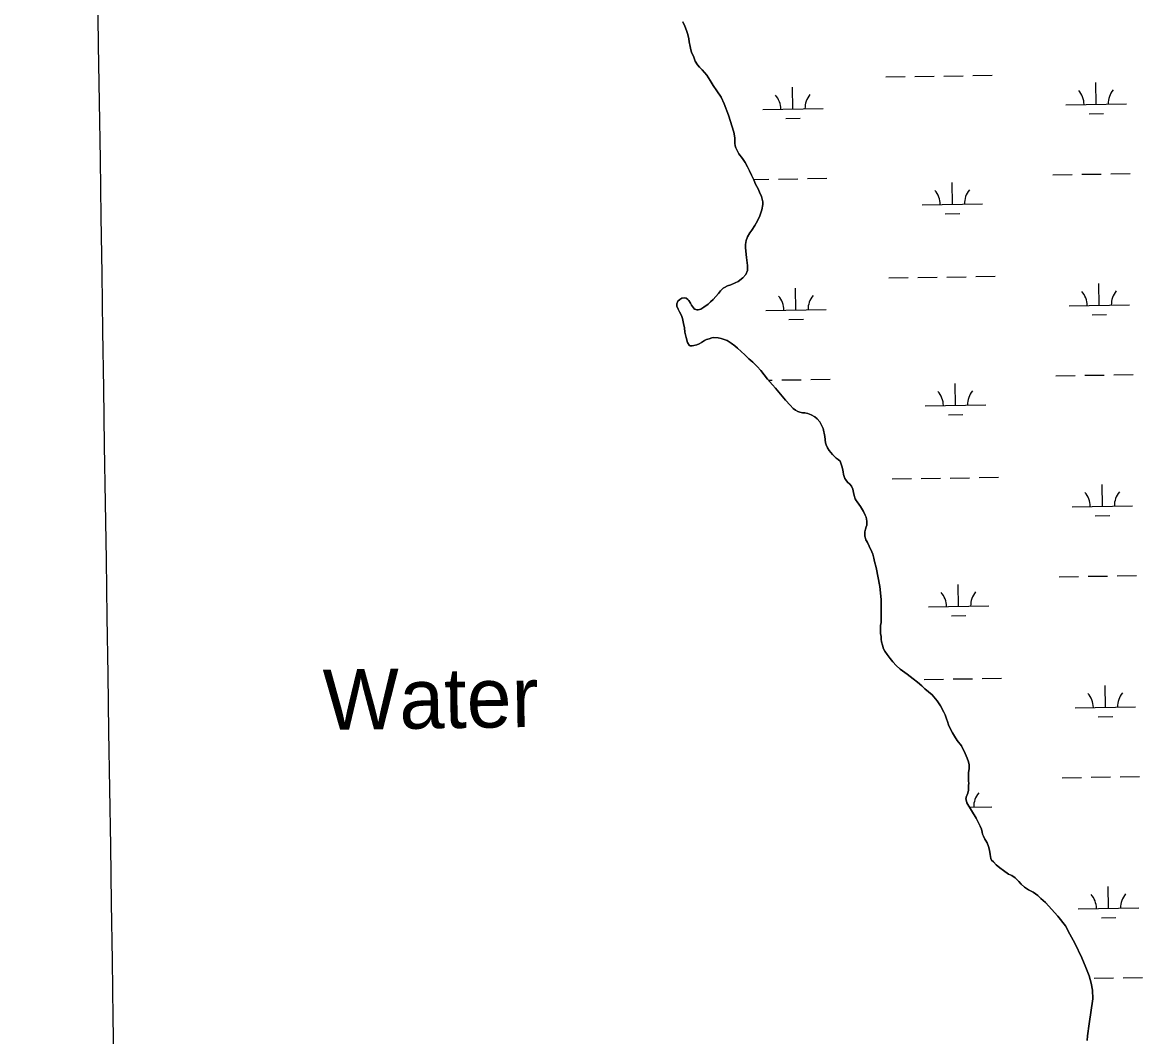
# Model space of a CAD drawing. Extents: x 3823584 to 3861785, y 301729 to 327625.
# Drawn here: x 3832860 to 3834714, y 315442 to 317121 of the extents above; entities that cross this region are included whole.
import ezdxf

# ---------------------------------------------------------------- set-up
doc = ezdxf.new("R2010")
doc.units = 0
for name, color, linetype in [('V-GRID-MAJR', 7, 'Continuous'), ('V-RIVR-IDEN', 7, 'Continuous'), ('V-TOPO-SHOR', 7, 'Continuous'), ('V-WETL-SWMP', 7, 'Continuous')]:
    doc.layers.add(name, color=color, linetype=linetype)

msp = doc.modelspace()

# ---------------------------------------------------------------- linework, layer by layer
at = {"layer": 'V-GRID-MAJR'}
msp.add_spline([(3833134.7290000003, 307237.467), (3833043.082, 313295.662), (3832951.406, 319355.783), (3832859.73, 325415.89900000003), (3832859.701, 325417.829)], degree=3, dxfattribs=at)
at = {"layer": 'V-TOPO-SHOR'}
for points in [[(3833952.44, 317121.92), (3833956.2, 317114.297), (3833958.897, 317107.457), (3833960.804, 317100.61), (3833962.448, 317093.498), (3833963.2800000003, 317088.754), (3833964.664, 317081.11100000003), (3833966.0300000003, 317075.58), (3833966.858, 317071.627), (3833970.626, 317062.95), (3833973.319, 317056.63800000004), (3833977.065, 317050.598), (3833980.2660000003, 317046.666), (3833984.528, 317042.216), (3833992.521, 317033.309), (3833998.139, 317024.646), (3834002.958, 317016.505), (3834009.106, 317007.582), (3834016.057, 316997.08400000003)], [(3834016.057, 316997.08400000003), (3834021.167, 316986.041), (3834028.187, 316967.359), (3834036.873, 316939.191), (3834038.8000000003, 316929.969), (3834038.8370000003, 316925.482), (3834038.878, 316920.732), (3834039.443, 316916.249), (3834040.262, 316913.089), (3834042.413, 316908.621), (3834045.6240000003, 316903.367), (3834051.5, 316895.237), (3834056.042, 316888.675), (3834059.796, 316881.84500000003), (3834063.022, 316875.009), (3834066.2490000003, 316867.91000000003), (3834070.009, 316860.288), (3834072.975, 316853.185), (3834077.265, 316845.04), (3834079.684, 316840.045), (3834082.916, 316832.419), (3834084.8370000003, 316823.987), (3834085.14, 316819.24), (3834083.629, 316810.779), (3834080.282, 316800.722), (3834076.129, 316792.503), (3834071.7090000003, 316784.549), (3834066.757, 316777.114), (3834063.632, 316772.338), (3834059.4620000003, 316765.967), (3834057.404, 316759.614), (3834056.1380000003, 316753.27), (3834056.183, 316747.992), (3834057.3340000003, 316736.65), (3834058.17, 316731.643), (3834059.298, 316722.943), (3834059.8680000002, 316718.195), (3834059.657, 316711.859), (3834059.673, 316710.012), (3834057.089, 316703.655), (3834052.122, 316697.806), (3834043.99, 316691.93), (3834039.523, 316689.515), (3834031.896, 316686.284), (3834026.631, 316684.655), (3834021.636, 316682.237), (3834019.536, 316680.89900000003), (3834014.824, 316676.371), (3834011.43, 316671.855), (3834007.248, 316667.069), (3834003.0640000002, 316662.283), (3833998.348, 316658.283), (3833994.4220000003, 316654.556), (3833987.34, 316649.217), (3833982.3510000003, 316646.006), (3833978.134, 316645.178), (3833976.0270000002, 316644.898), (3833974.437, 316645.412), (3833973.114, 316645.928), (3833972.056, 316646.184), (3833970.454, 316648.281), (3833967.247, 316653.004), (3833965.373, 316656.155), (3833962.696, 316660.356), (3833961.099, 316662.191), (3833958.44, 316664.28), (3833956.059, 316665.052), (3833951.049, 316664.216), (3833947.637, 316662.076), (3833944.231, 316659.143), (3833942.947, 316654.91000000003), (3833942.98, 316650.951), (3833944.87, 316645.952), (3833947.2830000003, 316641.48600000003), (3833950.238, 316635.44), (3833952.127, 316630.705), (3833954.043, 316622.538), (3833955.164, 316615.157), (3833956.014, 316608.302), (3833957.937, 316599.344), (3833960.644, 316591.185), (3833963.323, 316586.718), (3833964.6520000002, 316585.676), (3833965.973, 316585.422), (3833968.349, 316585.442), (3833970.987, 316585.729), (3833975.7260000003, 316587.089), (3833979.934, 316588.70900000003), (3833983.61, 316591.115), (3833988.599, 316594.06), (3833991.753, 316595.672), (3833996.49, 316597.29600000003), (3834000.703, 316598.652), (3834004.127, 316599.473), (3834011.2600000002, 316598.742), (3834016.02, 316597.726), (3834026.08, 316594.115), (3834032.715, 316589.95), (3834038.558, 316585.512), (3834043.076, 316581.854), (3834049.464, 316575.839)], [(3834049.464, 316575.839), (3834055.0530000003, 316570.342), (3834061.969, 316564.065), (3834068.3510000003, 316558.576), (3834075.8030000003, 316551.251), (3834081.669, 316544.43700000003), (3834087.272, 316537.357), (3834092.8710000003, 316530.543), (3834100.873, 316520.844), (3834106.2, 316515.347), (3834122.469, 316495.424), (3834130.4560000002, 316487.31), (3834135.255, 316481.80700000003), (3834139.238, 316478.94), (3834142.953, 316476.59500000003), (3834146.394, 316475.569), (3834150.887, 316474.813), (3834154.852, 316474.32), (3834159.347, 316473.302), (3834165.17, 316471.504), (3834171.269, 316468.124), (3834175.258, 316464.463), (3834179.258, 316459.746), (3834184.894, 316448.707), (3834187.649, 316435.27), (3834189.056, 316424.987), (3834190.139, 316421.829), (3834192.031, 316416.566), (3834194.708, 316412.101), (3834197.377, 316408.694), (3834200.307, 316405.552), (3834203.236, 316402.672), (3834206.427, 316399.795), (3834209.613, 316397.44800000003), (3834212.806, 316394.571), (3834214.961, 316389.575), (3834216.044, 316386.153), (3834216.869, 316382.201), (3834217.973, 316376.667), (3834218.801, 316372.45), (3834220.967, 316365.87), (3834222.309, 316363.506), (3834225.244, 316359.836), (3834228.967, 316356.43700000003), (3834231.9, 316353.029), (3834234.0500000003, 316348.298), (3834235.156, 316342.498), (3834235.992, 316337.491), (3834237.6180000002, 316332.49), (3834239.49, 316329.602), (3834241.093, 316327.24), (3834244.0300000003, 316323.306), (3834246.701, 316319.632), (3834251.788, 316311.229), (3834254.213, 316305.444), (3834255.826, 316301.761), (3834257.203, 316295.175), (3834257.225, 316292.53500000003), (3834256.992, 316288.838), (3834256.2260000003, 316285.928), (3834255.204, 316281.961), (3834253.9220000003, 316277.464), (3834253.934, 316275.879), (3834253.701, 316272.446), (3834253.981, 316270.337), (3834254.2600000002, 316268.756), (3834255.616, 316264.543), (3834256.685, 316262.968), (3834258.0300000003, 316259.81200000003), (3834261.25, 316253.768), (3834265.5500000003, 316244.569), (3834266.9020000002, 316240.885), (3834268.545, 316234.036), (3834269.913, 316228.24), (3834272.897, 316218.762), (3834278.971, 316187.403), (3834281.005, 316165.514), (3834280.861, 316151.26), (3834280.9620000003, 316139.382), (3834280.7630000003, 316131.726), (3834280.798, 316127.767), (3834280.048, 316122.746), (3834279.557, 316118.51900000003), (3834279.606, 316112.71), (3834279.897, 316109.54600000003), (3834280.73, 316104.539), (3834281.0330000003, 316100.054), (3834281.599, 316095.57300000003), (3834282.969, 316089.777), (3834284.865, 316083.985), (3834287.009, 316080.045), (3834290.751, 316074.534), (3834295.56, 316067.976), (3834300.358, 316062.20900000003), (3834305.687, 316056.44800000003), (3834312.3370000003, 316050.433), (3834323.757, 316042.083), (3834333.8510000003, 316034.516), (3834340.7630000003, 316028.767), (3834347.943, 316022.494), (3834353, 316017.786)], [(3834353, 316017.786), (3834365.491, 316007.597), (3834373.759, 315997.637), (3834379.106, 315989.501), (3834384.472, 315979.25), (3834386.6240000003, 315974.52), (3834388.789, 315968.202), (3834390.411, 315963.729), (3834392.307, 315957.939), (3834394.998, 315951.889), (3834398.752, 315945.059), (3834402.4960000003, 315939.284), (3834406.514, 315932.456), (3834413.715, 315923.543), (3834420.16, 315910.663), (3834423.13, 315903.034), (3834425.294, 315896.718), (3834426.39, 315891.977), (3834426.677, 315889.339), (3834426.449, 315885.114), (3834425.44, 315879.56200000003), (3834425.219, 315874.544), (3834425.528, 315869.26900000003), (3834425.571, 315864.253), (3834425.8510000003, 315862.146), (3834425.628, 315857.392), (3834425.167, 315849.469), (3834424.918, 315847.884), (3834424.147, 315845.238), (3834421.829, 315838.618), (3834421.575, 315837.297), (3834421.059, 315835.972), (3834422.698, 315829.652), (3834422.702, 315829.124), (3834438.227, 315803.653), (3834444.673, 315790.511), (3834446.825, 315785.778), (3834447.9250000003, 315780.773), (3834448.7460000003, 315777.082), (3834450.096, 315773.662), (3834452.5100000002, 315768.933), (3834453.846, 315767.36), (3834456.2600000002, 315762.629), (3834458.421, 315756.842), (3834460.055, 315750.784), (3834461.173, 315743.667), (3834462.2830000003, 315737.079), (3834463.629, 315734.18700000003), (3834466.822, 315731.309), (3834471.348, 315726.597), (3834477.197, 315721.63), (3834483.572, 315716.934), (3834491.539, 315711.196), (3834497.103, 315708.603), (3834502.6780000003, 315704.956), (3834508.535, 315698.935), (3834512.799, 315694.218), (3834518.122, 315689.25), (3834524.751, 315685.346), (3834532.4420000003, 315681.189), (3834540.14, 315675.974), (3834545.199, 315671.004), (3834552.649, 315663.938), (3834573.164, 315641.414), (3834585.7060000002, 315625.42), (3834593.214, 315611.757), (3834601.259, 315596.78), (3834612.815, 315572.59500000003), (3834619.811, 315556.818), (3834625.2120000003, 315542.61100000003), (3834628.481, 315530.49700000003), (3834630.4280000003, 315518.89900000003), (3834631.338, 315504.917), (3834625.3570000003, 315463.163), (3834622.359, 315443.34), (3834621.632, 315435.681)]]:
    msp.add_lwpolyline(points, dxfattribs=at)
at = {"layer": 'V-WETL-SWMP'}
for p, q in [((3834288.620041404, 317030.48119990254), (3834320.616238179, 317030.9745403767)), ((3834336.614336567, 317031.2212106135), (3834368.610533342, 317031.7145510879)), ((3834384.60863173, 317031.9612213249), (3834416.604828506, 317032.45456179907)), ((3834432.602926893, 317032.7012320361), (3834464.599123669, 317033.1945725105)), ((3834134.82870057, 316977.3619086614), (3834134.2736911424, 317013.3576258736)), ((3834636.6770484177, 316985.0997689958), (3834636.1220389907, 317021.095486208)), ((3834084.8346431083, 316976.5910641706), (3834184.8227580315, 316978.1327531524)), ((3834586.6829909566, 316984.328924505), (3834686.6711058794, 316985.8706134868)), ((3834123.068025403, 316961.7477417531), (3834147.0651729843, 316962.1177471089)), ((3834624.916373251, 316969.4856020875), (3834648.913520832, 316969.8556074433)), ((3834069.7025161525, 316860.9120393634), (3834095.2052288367, 316861.3052586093)), ((3834111.2033272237, 316861.55192884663), (3834143.1995239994, 316862.0452693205)), ((3834159.197622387, 316862.2919395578), (3834191.1938191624, 316862.7852800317)), ((3834565.057379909, 316868.54977846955), (3834597.0535766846, 316869.0431189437)), ((3834613.051675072, 316869.289789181), (3834645.047871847, 316869.7831296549)), ((3834661.045970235, 316870.0297998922), (3834693.0421670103, 316870.5231403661)), ((3834398.7290435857, 316819.54969479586), (3834398.1740341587, 316855.54541200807)), ((3834348.734986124, 316818.77885030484), (3834448.7231010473, 316820.32053928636)), ((3834386.968368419, 316803.93552788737), (3834410.965516, 316804.30553324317)), ((3834293.7488681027, 316697.84577702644), (3834325.745064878, 316698.3391175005)), ((3834341.7431632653, 316698.5857877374), (3834373.7393600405, 316699.0791282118)), ((3834389.7374584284, 316699.3257984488), (3834421.733655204, 316699.81913892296)), ((3834437.7317535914, 316700.06580916), (3834469.727950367, 316700.5591496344)), ((3834139.9575272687, 316644.7264857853), (3834139.402517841, 316680.7222029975)), ((3834641.8058751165, 316652.46434611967), (3834641.2508656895, 316688.4600633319)), ((3834089.9634698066, 316643.9556412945), (3834189.9515847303, 316645.49733027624)), ((3834591.811817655, 316651.6935016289), (3834691.799932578, 316653.23519061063)), ((3834128.1968521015, 316629.112318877), (3834152.1939996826, 316629.4823242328)), ((3834630.0451999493, 316636.8501792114), (3834654.0423475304, 316637.2201845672)), ((3834094.4923215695, 316528.5797636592), (3834100.334055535, 316528.6698357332)), ((3834116.332153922, 316528.91650597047), (3834148.3283506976, 316529.4098464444)), ((3834164.3264490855, 316529.65651668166), (3834196.3226458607, 316530.1498571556)), ((3834570.186206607, 316535.91435559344), (3834602.182403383, 316536.4076960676)), ((3834618.18050177, 316536.65436630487), (3834650.1766985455, 316537.1477067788)), ((3834666.1747969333, 316537.39437701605), (3834698.1709937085, 316537.88771748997)), ((3834403.857870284, 316486.91427191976), (3834403.302860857, 316522.9099891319)), ((3834353.8638128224, 316486.14342742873), (3834453.8519277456, 316487.68511641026)), ((3834392.0971951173, 316471.3001050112), (3834416.0943426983, 316471.67011036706)), ((3834298.877694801, 316365.2103541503), (3834330.873891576, 316365.7036946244)), ((3834346.8719899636, 316365.95036486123), (3834378.8681867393, 316366.4437053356)), ((3834394.8662851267, 316366.6903755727), (3834426.8624819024, 316367.1837160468)), ((3834442.8605802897, 316367.4303862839), (3834474.8567770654, 316367.9237267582)), ((3834646.934701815, 316319.8289232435), (3834646.3796923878, 316355.8246404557)), ((3834596.940644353, 316319.0580787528), (3834696.9287592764, 316320.59976773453)), ((3834635.1740266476, 316304.21475633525), (3834659.1711742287, 316304.5847616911)), ((3834575.315033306, 316203.27893271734), (3834607.3112300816, 316203.7722731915)), ((3834623.309328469, 316204.01894342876), (3834655.3055252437, 316204.5122839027)), ((3834671.3036236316, 316204.75895413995), (3834703.299820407, 316205.25229461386)), ((3834408.9866969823, 316154.2788490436), (3834408.4316875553, 316190.2745662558)), ((3834358.992639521, 316153.5080045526), (3834458.9807544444, 316155.04969353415)), ((3834397.2260218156, 316138.6646821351), (3834421.223169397, 316139.03468749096)), ((3834335.600170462, 316033.06206497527), (3834336.002718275, 316033.0682717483)), ((3834352.0008166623, 316033.3149419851), (3834383.997013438, 316033.8082824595)), ((3834399.9951118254, 316034.05495269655), (3834431.991308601, 316034.5482931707)), ((3834447.9894069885, 316034.79496340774), (3834479.9856037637, 316035.2883038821)), ((3834652.063528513, 315987.1935003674), (3834651.508519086, 316023.1892175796)), ((3834602.0694710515, 315986.42265587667), (3834702.0575859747, 315987.9643448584)), ((3834640.302853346, 315971.57933345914), (3834664.3000009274, 315971.949338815)), ((3834580.4438600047, 315870.64350984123), (3834612.44005678, 315871.1368503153)), ((3834628.4381551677, 315871.38352055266), (3834660.4343519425, 315871.8768610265)), ((3834676.4324503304, 315872.12353126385), (3834708.4286471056, 315872.6168717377)), ((3834427.1390299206, 315821.8442319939), (3834464.1095811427, 315822.41427065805)), ((3834657.1923552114, 315654.5580774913), (3834656.6373457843, 315690.5537947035)), ((3834607.19829775, 315653.7872330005), (3834707.186412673, 315655.3289219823)), ((3834645.4316800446, 315638.94391058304), (3834669.428827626, 315639.31391593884)), ((3834633.566981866, 315538.74809767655), (3834665.5631786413, 315539.2414381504)), ((3834681.561277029, 315539.48810838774), (3834713.5574738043, 315539.9814488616))]:
    msp.add_line(p, q, dxfattribs=at)
for points in [[(3833974.438, 316645.411), (3833976.026, 316644.897), (3833978.1350000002, 316645.178), (3833982.3510000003, 316646.006), (3833987.339, 316649.216), (3833994.421, 316654.555), (3833998.348, 316658.284), (3834003.065, 316662.283), (3834007.248, 316667.07), (3834011.43, 316671.856), (3834014.823, 316676.37200000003), (3834019.536, 316680.9), (3834021.636, 316682.237), (3834026.631, 316684.655), (3834031.896, 316686.284), (3834039.523, 316689.516), (3834043.99, 316691.93), (3834052.122, 316697.806), (3834057.088, 316703.655), (3834059.673, 316710.011), (3834059.657, 316711.859), (3834059.867, 316718.196), (3834059.299, 316722.942), (3834058.17, 316731.643), (3834057.335, 316736.651), (3834056.183, 316747.991), (3834056.1380000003, 316753.26900000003), (3834057.404, 316759.615), (3834059.4620000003, 316765.967), (3834063.631, 316772.338), (3834066.757, 316777.115), (3834071.7090000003, 316784.548), (3834076.129, 316792.504), (3834080.282, 316800.722), (3834083.628, 316810.78), (3834085.14, 316819.24), (3834084.836, 316823.988), (3834082.916, 316832.418), (3834079.684, 316840.045), (3834077.2660000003, 316845.04), (3834072.974, 316853.186), (3834070.0100000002, 316860.288), (3834066.25, 316867.91000000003), (3834063.022, 316875.009), (3834059.7970000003, 316881.84500000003), (3834056.043, 316888.676), (3834051.5, 316895.23600000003), (3834045.6240000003, 316903.368), (3834042.412, 316908.62), (3834040.2630000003, 316913.089), (3834039.444, 316916.249), (3834038.878, 316920.732), (3834038.8370000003, 316925.482), (3834038.799, 316929.969), (3834036.873, 316939.191), (3834028.188, 316967.36), (3834021.166, 316986.041), (3834016.057, 316997.08400000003), (3834009.105, 317007.583), (3834002.958, 317016.505), (3833998.1380000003, 317024.646), (3833992.522, 317033.309), (3833984.5270000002, 317042.215), (3833980.2660000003, 317046.666), (3833977.065, 317050.598), (3833973.319, 317056.637), (3833970.626, 317062.949), (3833966.8570000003, 317071.628), (3833966.031, 317075.58), (3833964.664, 317081.11100000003), (3833963.2800000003, 317088.754), (3833962.448, 317093.498), (3833960.8030000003, 317100.61100000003), (3833958.898, 317107.457), (3833956.2, 317114.297), (3833952.44, 317121.92)], [(3834257.225, 316292.536), (3834257.203, 316295.175), (3834255.827, 316301.762), (3834254.2120000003, 316305.444), (3834251.787, 316311.23), (3834246.701, 316319.63300000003), (3834244.0300000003, 316323.306), (3834241.093, 316327.24), (3834239.489, 316329.602), (3834237.617, 316332.49), (3834235.991, 316337.491), (3834235.156, 316342.499), (3834234.051, 316348.297), (3834231.9, 316353.029), (3834228.967, 316356.436), (3834225.2430000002, 316359.836), (3834222.308, 316363.506), (3834220.968, 316365.87), (3834218.801, 316372.451), (3834217.973, 316376.667), (3834216.87, 316382.2), (3834216.045, 316386.153), (3834214.96, 316389.575), (3834212.806, 316394.571), (3834209.614, 316397.44800000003), (3834206.427, 316399.79600000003), (3834203.235, 316402.673), (3834200.307, 316405.551), (3834197.377, 316408.694), (3834194.708, 316412.102), (3834192.031, 316416.567), (3834190.1380000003, 316421.83), (3834189.056, 316424.988), (3834187.649, 316435.27), (3834184.895, 316448.708), (3834179.258, 316459.746), (3834175.259, 316464.463), (3834171.268, 316468.125), (3834165.169, 316471.504), (3834159.347, 316473.302), (3834154.8510000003, 316474.32), (3834150.887, 316474.814), (3834146.394, 316475.568), (3834142.954, 316476.59500000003), (3834139.238, 316478.939), (3834135.255, 316481.808), (3834130.457, 316487.31), (3834122.469, 316495.425), (3834106.199, 316515.347), (3834100.873, 316520.84500000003), (3834092.872, 316530.543), (3834087.272, 316537.358), (3834081.668, 316544.43700000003), (3834075.804, 316551.25), (3834068.3510000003, 316558.577), (3834061.969, 316564.066), (3834055.0530000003, 316570.342), (3834049.463, 316575.838), (3834043.077, 316581.854), (3834038.559, 316585.511), (3834032.715, 316589.949), (3834026.08, 316594.115), (3834016.02, 316597.72500000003), (3834011.2600000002, 316598.741), (3834004.127, 316599.472), (3834000.703, 316598.651), (3833996.491, 316597.295), (3833991.754, 316595.67100000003), (3833988.6, 316594.061), (3833983.61, 316591.115), (3833979.935, 316588.708), (3833975.725, 316587.089), (3833970.986, 316585.729), (3833968.349, 316585.442), (3833965.973, 316585.422), (3833964.6520000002, 316585.675), (3833963.323, 316586.719), (3833960.645, 316591.184), (3833957.937, 316599.343), (3833956.0130000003, 316608.301), (3833955.163, 316615.157), (3833954.044, 316622.538), (3833952.127, 316630.704), (3833950.239, 316635.439), (3833947.284, 316641.485), (3833944.8710000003, 316645.952), (3833942.981, 316650.951), (3833942.947, 316654.91000000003), (3833944.231, 316659.14400000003), (3833947.637, 316662.076), (3833951.0500000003, 316664.217), (3833956.058, 316665.051), (3833958.441, 316664.279), (3833961.098, 316662.19), (3833962.697, 316660.356), (3833965.372, 316656.156), (3833967.247, 316653.004), (3833970.454, 316648.281), (3833972.056, 316646.183), (3833973.114, 316645.928), (3833974.438, 316645.411)], [(3834518.1210000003, 315689.249), (3834512.799, 315694.219), (3834508.536, 315698.934), (3834502.6780000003, 315704.955), (3834497.1040000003, 315708.603), (3834491.539, 315711.195), (3834483.572, 315716.934), (3834477.197, 315721.631), (3834471.348, 315726.597), (3834466.821, 315731.309), (3834463.629, 315734.186), (3834462.284, 315737.078), (3834461.173, 315743.667), (3834460.056, 315750.784), (3834458.421, 315756.841), (3834456.2600000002, 315762.63), (3834453.845, 315767.36), (3834452.511, 315768.933), (3834450.096, 315773.663), (3834448.747, 315777.083), (3834447.924, 315780.772), (3834446.825, 315785.777), (3834444.673, 315790.51), (3834438.227, 315803.653), (3834422.701, 315829.124), (3834422.697, 315829.652), (3834421.059, 315835.973), (3834421.576, 315837.297), (3834421.829, 315838.619), (3834424.148, 315845.238), (3834424.917, 315847.884), (3834425.168, 315849.469), (3834425.628, 315857.392), (3834425.852, 315862.145), (3834425.5700000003, 315864.254), (3834425.528, 315869.26900000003), (3834425.219, 315874.545), (3834425.44, 315879.56200000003), (3834426.449, 315885.114), (3834426.677, 315889.339), (3834426.39, 315891.976), (3834425.294, 315896.718), (3834423.129, 315903.034), (3834420.161, 315910.663), (3834413.716, 315923.542), (3834406.514, 315932.455), (3834402.497, 315939.284), (3834398.752, 315945.059), (3834394.9990000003, 315951.89), (3834392.308, 315957.938), (3834390.411, 315963.729), (3834388.789, 315968.202), (3834386.6240000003, 315974.51900000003), (3834384.472, 315979.251), (3834379.106, 315989.5), (3834373.758, 315997.637), (3834365.491, 316007.597), (3834352.9990000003, 316017.78500000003), (3834347.944, 316022.493), (3834340.764, 316028.767), (3834333.852, 316034.515), (3834323.757, 316042.08400000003), (3834312.3370000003, 316050.433), (3834305.687, 316056.44800000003), (3834300.359, 316062.20900000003), (3834295.559, 316067.97500000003), (3834290.752, 316074.533), (3834287.0100000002, 316080.044), (3834284.865, 316083.985), (3834282.968, 316089.776), (3834281.599, 316095.572), (3834281.0330000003, 316100.054), (3834280.731, 316104.538), (3834279.896, 316109.54600000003), (3834279.605, 316112.711), (3834279.556, 316118.518), (3834280.048, 316122.745), (3834280.7970000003, 316127.767), (3834280.7630000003, 316131.726), (3834280.9620000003, 316139.382), (3834280.861, 316151.259), (3834281.004, 316165.514), (3834278.971, 316187.404), (3834272.897, 316218.76300000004), (3834269.913, 316228.24), (3834268.544, 316234.03500000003), (3834266.9020000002, 316240.884), (3834265.551, 316244.568), (3834261.25, 316253.76900000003), (3834258.031, 316259.813), (3834256.684, 316262.969), (3834255.615, 316264.543), (3834254.2600000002, 316268.755), (3834253.9820000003, 316270.336), (3834253.7, 316272.446), (3834253.935, 316275.879), (3834253.9220000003, 316277.463), (3834255.203, 316281.961), (3834256.225, 316285.929), (3834256.992, 316288.839), (3834257.225, 316292.536)], [(3834621.633, 315435.68), (3834622.359, 315443.341), (3834625.358, 315463.162), (3834631.338, 315504.918), (3834630.4280000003, 315518.89900000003), (3834628.481, 315530.49700000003), (3834625.211, 315542.61100000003), (3834619.811, 315556.818), (3834612.815, 315572.596), (3834601.259, 315596.781), (3834593.213, 315611.75800000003), (3834585.707, 315625.419), (3834573.165, 315641.414), (3834552.649, 315663.939), (3834545.199, 315671.003), (3834540.1410000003, 315675.97500000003), (3834532.4420000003, 315681.188), (3834524.752, 315685.346), (3834518.1210000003, 315689.249)]]:
    msp.add_lwpolyline(points, dxfattribs=at)
for centre, radius, start, end in [((3834079.5850101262, 316976.98498109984), 35.24628790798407, 0.11153774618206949, 41.655196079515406), ((3834190.0577509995, 316978.68832961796), 35.24628790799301, 140.11153456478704, 181.65519289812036), ((3834581.433357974, 316984.72284143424), 35.24628790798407, 0.11153774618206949, 41.655196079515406), ((3834691.9060988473, 316986.42618995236), 35.24628790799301, 140.11153456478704, 181.65519289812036), ((3834453.9580940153, 316820.87611575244), 35.24628790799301, 140.11153456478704, 181.65519289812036), ((3834343.4853531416, 316819.1727672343), 35.24628790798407, 0.11153774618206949, 41.655196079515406), ((3834697.034925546, 316653.79076707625), 35.24628790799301, 140.11153456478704, 181.65519289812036), ((3834084.7138368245, 316644.34955822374), 35.24628790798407, 0.11153774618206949, 41.655196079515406), ((3834195.186577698, 316646.05290674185), 35.24628790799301, 140.11153456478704, 181.65519289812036), ((3834586.5621846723, 316652.08741855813), 35.24628790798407, 0.11153774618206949, 41.655196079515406), ((3834348.61417984, 316486.5373443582), 35.24628790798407, 0.11153774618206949, 41.655196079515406), ((3834459.0869207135, 316488.24069287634), 35.24628790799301, 140.11153456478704, 181.65519289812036), ((3834591.6910113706, 316319.45199568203), 35.24628790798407, 0.11153774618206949, 41.655196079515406), ((3834702.1637522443, 316321.15534420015), 35.24628790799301, 140.11153456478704, 181.65519289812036), ((3834353.7430065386, 316153.9019214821), 35.24628790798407, 0.11153774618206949, 41.655196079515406), ((3834464.2157474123, 316155.60527000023), 35.24628790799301, 140.11153456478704, 181.65519289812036), ((3834596.819838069, 315986.81657280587), 35.24628790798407, 0.11153774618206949, 41.655196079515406), ((3834707.2925789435, 315988.51992132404), 35.24628790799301, 140.11153456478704, 181.65519289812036), ((3834469.344574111, 315822.9698471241), 35.24628790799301, 140.11153456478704, 181.65519289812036), ((3834601.9486647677, 315654.18114992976), 35.24628790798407, 0.11153774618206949, 41.655196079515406), ((3834712.421405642, 315655.8844984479), 35.24628790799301, 140.11153456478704, 181.65519289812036)]:
    msp.add_arc(centre, radius, start, end, dxfattribs=at)

# ---------------------------------------------------------------- texts
at = {"layer": 'V-RIVR-IDEN'}
msp.add_text('Water', height=99.99980199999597, rotation=0.8425138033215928, dxfattribs=at).set_placement((3833357.8132449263, 315949.56407549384))

doc.saveas('drawing.dxf')
